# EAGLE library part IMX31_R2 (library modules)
PVS (02/06/2008) pin name 2.775V changed in 3.1V CT (05/03/2008): split component in two symbols added all names to pins as in schematic of CPU-module rev120.
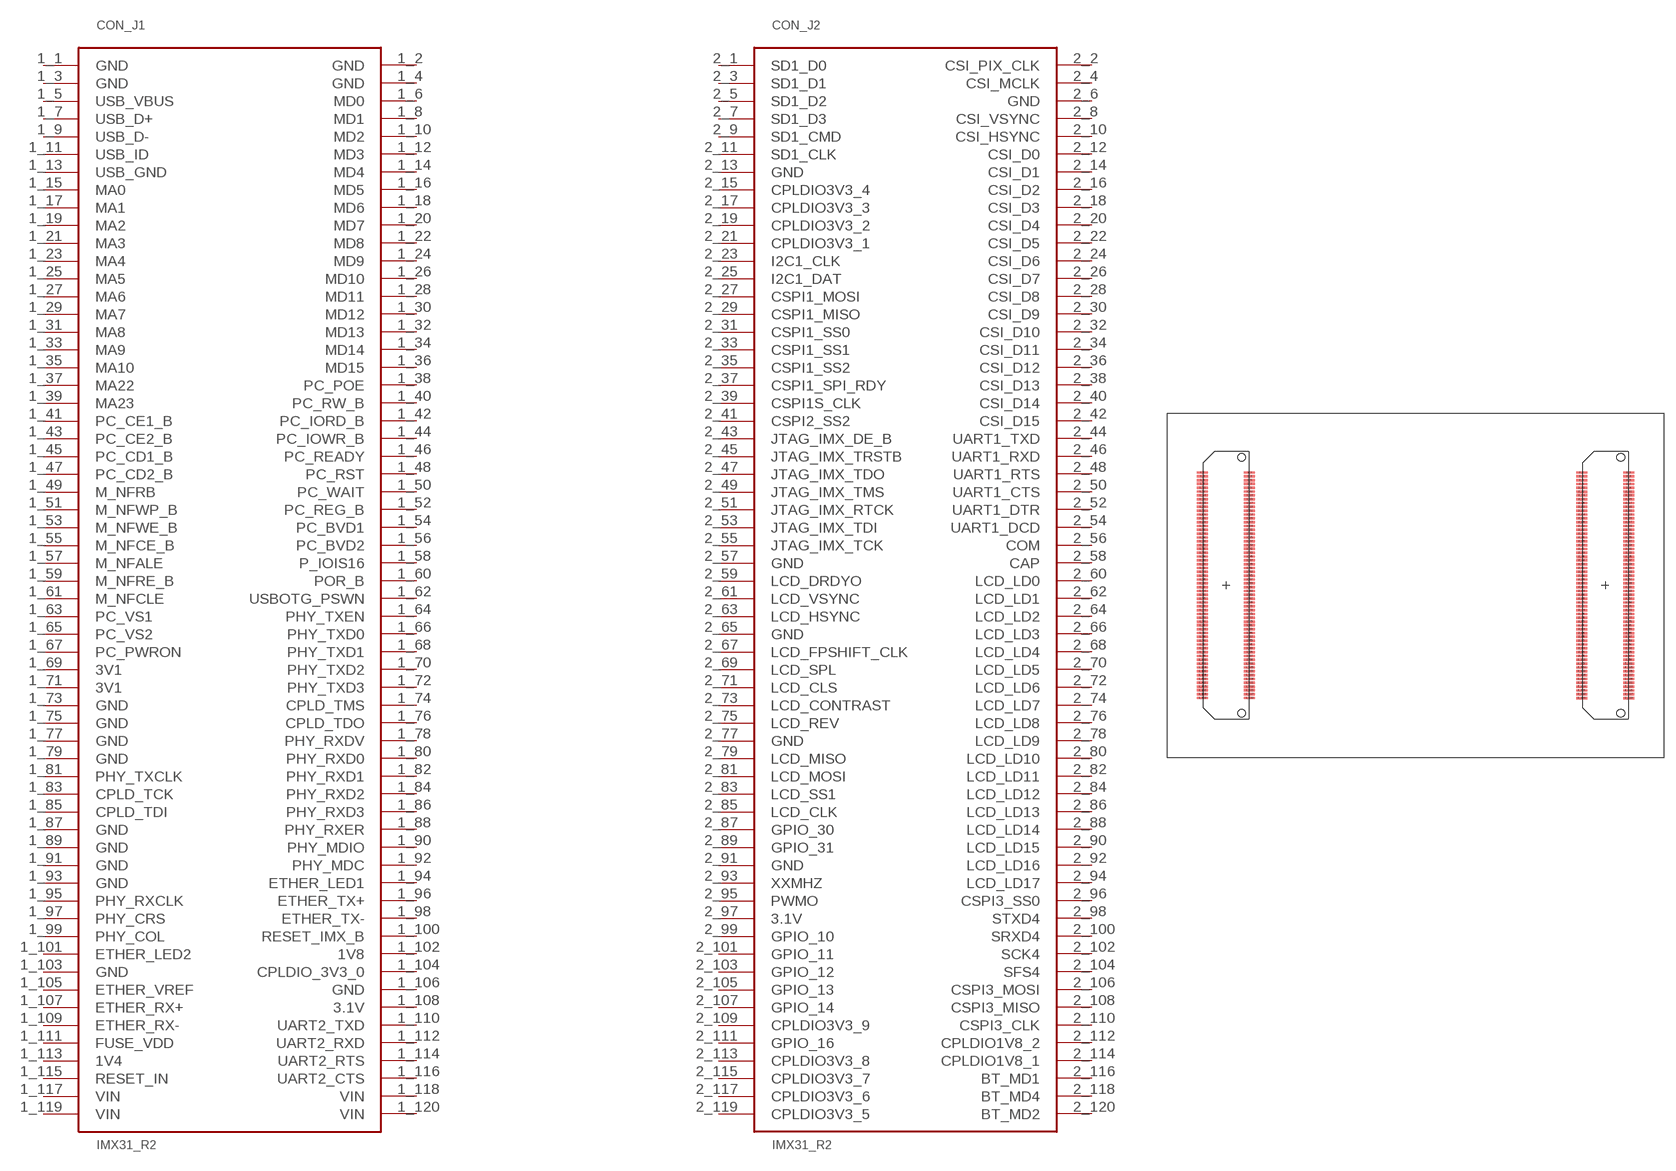
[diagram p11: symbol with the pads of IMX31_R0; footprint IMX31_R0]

Designator prefix CON; gates _J1=CPU_MODULE_J1-1 _J2=CPU_MODULE_J2-1

## IMX31_R2  [IMX31_R0]
1_1  _J1:GND
1_2  _J1:GND
1_3  _J1:GND
1_4  _J1:GND
1_5  _J1:USB_VBUS
1_6  _J1:MD0
1_7  _J1:USB_D+
1_8  _J1:MD1
1_9  _J1:USB_D-
1_10  _J1:MD2
1_11  _J1:USB_ID
1_12  _J1:MD3
1_13  _J1:USB_GND
1_14  _J1:MD4
1_15  _J1:MA0
1_16  _J1:MD5
1_17  _J1:MA1
1_18  _J1:MD6
1_19  _J1:MA2
1_20  _J1:MD7
1_21  _J1:MA3
1_22  _J1:MD8
1_23  _J1:MA4
1_24  _J1:MD9
1_25  _J1:MA5
1_26  _J1:MD10
1_27  _J1:MA6
1_28  _J1:MD11
1_29  _J1:MA7
1_30  _J1:MD12
1_31  _J1:MA8
1_32  _J1:MD13
1_33  _J1:MA9
1_34  _J1:MD14
1_35  _J1:MA10
1_36  _J1:MD15
1_37  _J1:MA22
1_38  _J1:PC_POE
1_39  _J1:MA23
1_40  _J1:PC_RW_B
1_41  _J1:PC_CE1_B
1_42  _J1:PC_IORD_B
1_43  _J1:PC_CE2_B
1_44  _J1:PC_IOWR_B
1_45  _J1:PC_CD1_B
1_46  _J1:PC_READY
1_47  _J1:PC_CD2_B
1_48  _J1:PC_RST
1_49  _J1:M_NFRB
1_50  _J1:PC_WAIT
1_51  _J1:M_NFWP_B
1_52  _J1:PC_REG_B
1_53  _J1:M_NFWE_B
1_54  _J1:PC_BVD1
1_55  _J1:M_NFCE_B
1_56  _J1:PC_BVD2
1_57  _J1:M_NFALE
1_58  _J1:P_IOIS16
1_59  _J1:M_NFRE_B
1_60  _J1:POR_B
1_61  _J1:M_NFCLE
1_62  _J1:USBOTG_PSWN
1_63  _J1:PC_VS1
1_64  _J1:PHY_TXEN
1_65  _J1:PC_VS2
1_66  _J1:PHY_TXD0
1_67  _J1:PC_PWRON
1_68  _J1:PHY_TXD1
1_69  _J1:3V1
1_70  _J1:PHY_TXD2
1_71  _J1:3V1
1_72  _J1:PHY_TXD3
1_73  _J1:GND
1_74  _J1:CPLD_TMS
1_75  _J1:GND
1_76  _J1:CPLD_TDO
1_77  _J1:GND
1_78  _J1:PHY_RXDV
1_79  _J1:GND
1_80  _J1:PHY_RXD0
1_81  _J1:PHY_TXCLK
1_82  _J1:PHY_RXD1
1_83  _J1:CPLD_TCK
1_84  _J1:PHY_RXD2
1_85  _J1:CPLD_TDI
1_86  _J1:PHY_RXD3
1_87  _J1:GND
1_88  _J1:PHY_RXER
1_89  _J1:GND
1_90  _J1:PHY_MDIO
1_91  _J1:GND
1_92  _J1:PHY_MDC
1_93  _J1:GND
1_94  _J1:ETHER_LED1
1_95  _J1:PHY_RXCLK
1_96  _J1:ETHER_TX+
1_97  _J1:PHY_CRS
1_98  _J1:ETHER_TX-
1_99  _J1:PHY_COL
1_100  _J1:RESET_IMX_B
1_101  _J1:ETHER_LED2
1_102  _J1:1V8
1_103  _J1:GND
1_104  _J1:CPLDIO_3V3_0
1_105  _J1:ETHER_VREF
1_106  _J1:GND
1_107  _J1:ETHER_RX+
1_108  _J1:3.1V
1_109  _J1:ETHER_RX-
1_110  _J1:UART2_TXD
1_111  _J1:FUSE_VDD
1_112  _J1:UART2_RXD
1_113  _J1:1V4
1_114  _J1:UART2_RTS
1_115  _J1:RESET_IN
1_116  _J1:UART2_CTS
1_117  _J1:VIN
1_118  _J1:VIN
1_119  _J1:VIN
1_120  _J1:VIN
2_1  _J2:SD1_D0
2_2  _J2:CSI_PIX_CLK
2_3  _J2:SD1_D1
2_4  _J2:CSI_MCLK
2_5  _J2:SD1_D2
2_6  _J2:GND
2_7  _J2:SD1_D3
2_8  _J2:CSI_VSYNC
2_9  _J2:SD1_CMD
2_10  _J2:CSI_HSYNC
2_11  _J2:SD1_CLK
2_12  _J2:CSI_D0
2_13  _J2:GND
2_14  _J2:CSI_D1
2_15  _J2:CPLDIO3V3_4
2_16  _J2:CSI_D2
2_17  _J2:CPLDIO3V3_3
2_18  _J2:CSI_D3
2_19  _J2:CPLDIO3V3_2
2_20  _J2:CSI_D4
2_21  _J2:CPLDIO3V3_1
2_22  _J2:CSI_D5
2_23  _J2:I2C1_CLK
2_24  _J2:CSI_D6
2_25  _J2:I2C1_DAT
2_26  _J2:CSI_D7
2_27  _J2:CSPI1_MOSI
2_28  _J2:CSI_D8
2_29  _J2:CSPI1_MISO
2_30  _J2:CSI_D9
2_31  _J2:CSPI1_SS0
2_32  _J2:CSI_D10
2_33  _J2:CSPI1_SS1
2_34  _J2:CSI_D11
2_35  _J2:CSPI1_SS2
2_36  _J2:CSI_D12
2_37  _J2:CSPI1_SPI_RDY
2_38  _J2:CSI_D13
2_39  _J2:CSPI1S_CLK
2_40  _J2:CSI_D14
2_41  _J2:CSPI2_SS2
2_42  _J2:CSI_D15
2_43  _J2:JTAG_IMX_DE_B
2_44  _J2:UART1_TXD
2_45  _J2:JTAG_IMX_TRSTB
2_46  _J2:UART1_RXD
2_47  _J2:JTAG_IMX_TDO
2_48  _J2:UART1_RTS
2_49  _J2:JTAG_IMX_TMS
2_50  _J2:UART1_CTS
2_51  _J2:JTAG_IMX_RTCK
2_52  _J2:UART1_DTR
2_53  _J2:JTAG_IMX_TDI
2_54  _J2:UART1_DCD
2_55  _J2:JTAG_IMX_TCK
2_56  _J2:COM
2_57  _J2:GND
2_58  _J2:CAP
2_59  _J2:LCD_DRDYO
2_60  _J2:LCD_LD0
2_61  _J2:LCD_VSYNC
2_62  _J2:LCD_LD1
2_63  _J2:LCD_HSYNC
2_64  _J2:LCD_LD2
2_65  _J2:GND
2_66  _J2:LCD_LD3
2_67  _J2:LCD_FPSHIFT_CLK
2_68  _J2:LCD_LD4
2_69  _J2:LCD_SPL
2_70  _J2:LCD_LD5
2_71  _J2:LCD_CLS
2_72  _J2:LCD_LD6
2_73  _J2:LCD_CONTRAST
2_74  _J2:LCD_LD7
2_75  _J2:LCD_REV
2_76  _J2:LCD_LD8
2_77  _J2:GND
2_78  _J2:LCD_LD9
2_79  _J2:LCD_MISO
2_80  _J2:LCD_LD10
2_81  _J2:LCD_MOSI
2_82  _J2:LCD_LD11
2_83  _J2:LCD_SS1
2_84  _J2:LCD_LD12
2_85  _J2:LCD_CLK
2_86  _J2:LCD_LD13
2_87  _J2:GPIO_30
2_88  _J2:LCD_LD14
2_89  _J2:GPIO_31
2_90  _J2:LCD_LD15
2_91  _J2:GND
2_92  _J2:LCD_LD16
2_93  _J2:XXMHZ
2_94  _J2:LCD_LD17
2_95  _J2:PWMO
2_96  _J2:CSPI3_SS0
2_97  _J2:3.1V
2_98  _J2:STXD4
2_99  _J2:GPIO_10
2_100  _J2:SRXD4
2_101  _J2:GPIO_11
2_102  _J2:SCK4
2_103  _J2:GPIO_12
2_104  _J2:SFS4
2_105  _J2:GPIO_13
2_106  _J2:CSPI3_MOSI
2_107  _J2:GPIO_14
2_108  _J2:CSPI3_MISO
2_109  _J2:CPLDIO3V3_9
2_110  _J2:CSPI3_CLK
2_111  _J2:GPIO_16
2_112  _J2:CPLDIO1V8_2
2_113  _J2:CPLDIO3V3_8
2_114  _J2:CPLDIO1V8_1
2_115  _J2:CPLDIO3V3_7
2_116  _J2:BT_MD1
2_117  _J2:CPLDIO3V3_6
2_118  _J2:BT_MD4
2_119  _J2:CPLDIO3V3_5
2_120  _J2:BT_MD2

## Footprint IMX31_R0 (pad centres in mm)
CT: 6 oct. 2008: changed drill of locking pins to 0.04" according to datasheet of -A option of connectors.
smd 1.448 x 0.305: 1_1 -21.714,14.755; 1_2 -27.886,14.755; 1_3 -21.714,14.255; 1_4 -27.886,14.255; 1_5 -21.714,13.755; 1_6 -27.886,13.755; 1_7 -21.714,13.255; 1_8 -27.886,13.255; 1_9 -21.714,12.755; 1_10 -27.886,12.755; 1_11 -21.714,12.255; 1_12 -27.886,12.255; 1_13 -21.714,11.755; 1_14 -27.886,11.755; 1_15 -21.714,11.255; 1_16 -27.886,11.255; 1_17 -21.714,10.755; 1_18 -27.886,10.755; 1_19 -21.714,10.255; 1_20 -27.886,10.255; 1_21 -21.714,9.755; 1_22 -27.886,9.755; 1_23 -21.714,9.255; 1_24 -27.886,9.255; 1_25 -21.714,8.755; 1_26 -27.886,8.755; 1_27 -21.714,8.255; 1_28 -27.886,8.255; 1_29 -21.714,7.755; 1_30 -27.886,7.755; 1_31 -21.714,7.255; 1_32 -27.886,7.255; 1_33 -21.714,6.755; 1_34 -27.886,6.755; 1_35 -21.714,6.255; 1_36 -27.886,6.255; 1_37 -21.714,5.755; 1_38 -27.886,5.755; 1_39 -21.714,5.255; 1_40 -27.886,5.255; 1_41 -21.714,4.755; 1_42 -27.886,4.755; 1_43 -21.714,4.255; 1_44 -27.886,4.255; 1_45 -21.714,3.755; 1_46 -27.886,3.755; 1_47 -21.714,3.255; 1_48 -27.886,3.255; 1_49 -21.714,2.755; 1_50 -27.886,2.755; 1_51 -21.714,2.255; 1_52 -27.886,2.255; 1_53 -21.714,1.755; 1_54 -27.886,1.755; 1_55 -21.714,1.255; 1_56 -27.886,1.255; 1_57 -21.714,0.755; 1_58 -27.886,0.755; 1_59 -21.714,0.255; 1_60 -27.886,0.255; 1_61 -21.714,-0.248; 1_62 -27.886,-0.248; 1_63 -21.714,-0.748; 1_64 -27.886,-0.748; 1_65 -21.714,-1.248; 1_66 -27.886,-1.248; 1_67 -21.714,-1.748; 1_68 -27.886,-1.748; 1_69 -21.714,-2.248; 1_70 -27.886,-2.248; 1_71 -21.714,-2.748; 1_72 -27.886,-2.748; 1_73 -21.714,-3.248; 1_74 -27.886,-3.248; 1_75 -21.714,-3.748; 1_76 -27.886,-3.748; 1_77 -21.714,-4.248; 1_78 -27.886,-4.248; 1_79 -21.714,-4.748; 1_80 -27.886,-4.748; 1_81 -21.714,-5.248; 1_82 -27.886,-5.248; 1_83 -21.714,-5.748; 1_84 -27.886,-5.748; 1_85 -21.714,-6.248; 1_86 -27.886,-6.248; 1_87 -21.714,-6.748; 1_88 -27.886,-6.748; 1_89 -21.714,-7.248; 1_90 -27.886,-7.248; 1_91 -21.714,-7.748; 1_92 -27.886,-7.748; 1_93 -21.714,-8.248; 1_94 -27.886,-8.248; 1_95 -21.714,-8.748; 1_96 -27.886,-8.748; 1_97 -21.714,-9.248; 1_98 -27.886,-9.248; 1_99 -21.714,-9.748; 1_100 -27.886,-9.748; 1_101 -21.714,-10.248; 1_102 -27.886,-10.248; 1_103 -21.714,-10.748; 1_104 -27.886,-10.748; 1_105 -21.714,-11.248; 1_106 -27.886,-11.248; 1_107 -21.714,-11.748; 1_108 -27.886,-11.748; 1_109 -21.714,-12.248; 1_110 -27.886,-12.248; 1_111 -21.714,-12.748; 1_112 -27.886,-12.748; 1_113 -21.714,-13.248; 1_114 -27.886,-13.248; 1_115 -21.714,-13.748; 1_116 -27.886,-13.748; 1_117 -21.714,-14.248; 1_118 -27.886,-14.248; 1_119 -21.714,-14.748; 1_120 -27.886,-14.748; 2_1 27.885,14.752; 2_2 21.713,14.752; 2_3 27.885,14.252; 2_4 21.713,14.252; 2_5 27.885,13.752; 2_6 21.713,13.752; 2_7 27.885,13.252; 2_8 21.713,13.252; 2_9 27.885,12.752; 2_10 21.713,12.752; 2_11 27.885,12.252; 2_12 21.713,12.252; 2_13 27.885,11.752; 2_14 21.713,11.752; 2_15 27.885,11.252; 2_16 21.713,11.252; 2_17 27.885,10.752; 2_18 21.713,10.752; 2_19 27.885,10.252; 2_20 21.713,10.252; 2_21 27.885,9.752; 2_22 21.713,9.752; 2_23 27.885,9.252; 2_24 21.713,9.252; 2_25 27.885,8.752; 2_26 21.713,8.752; 2_27 27.885,8.252; 2_28 21.713,8.252; 2_29 27.885,7.752; 2_30 21.713,7.752; 2_31 27.885,7.252; 2_32 21.713,7.252; 2_33 27.885,6.752; 2_34 21.713,6.752; 2_35 27.885,6.252; 2_36 21.713,6.252; 2_37 27.885,5.752; 2_38 21.713,5.752; 2_39 27.885,5.252; 2_40 21.713,5.252; 2_41 27.885,4.752; 2_42 21.713,4.752; 2_43 27.885,4.252; 2_44 21.713,4.252; 2_45 27.885,3.752; 2_46 21.713,3.752; 2_47 27.885,3.251; 2_48 21.713,3.251; 2_49 27.885,2.751; 2_50 21.713,2.751; 2_51 27.885,2.251; 2_52 21.713,2.251; 2_53 27.885,1.752; 2_54 21.713,1.752; 2_55 27.885,1.252; 2_56 21.713,1.252; 2_57 27.885,0.751; 2_58 21.713,0.751; 2_59 27.885,0.252; 2_60 21.713,0.252; 2_61 27.885,-0.252; 2_62 21.713,-0.252; 2_63 27.884,-0.754; 2_64 21.713,-0.751; 2_65 27.885,-1.252; 2_66 21.713,-1.252; 2_67 27.885,-1.752; 2_68 21.713,-1.752; 2_69 27.885,-2.252; 2_70 21.713,-2.252; 2_71 27.885,-2.752; 2_72 21.713,-2.752; 2_73 27.885,-3.252; 2_74 21.713,-3.252; 2_75 27.885,-3.752; 2_76 21.713,-3.752; 2_77 27.885,-4.252; 2_78 21.713,-4.252; 2_79 27.885,-4.752; 2_80 21.713,-4.752; 2_81 27.885,-5.252; 2_82 21.713,-5.252; 2_83 27.885,-5.752; 2_84 21.713,-5.752; 2_85 27.885,-6.252; 2_86 21.713,-6.252; 2_87 27.885,-6.752; 2_88 21.713,-6.752; 2_89 27.885,-7.252; 2_90 21.713,-7.252; 2_91 27.885,-7.752; 2_92 21.713,-7.752; 2_93 27.885,-8.252; 2_94 21.713,-8.252; 2_95 27.885,-8.752; 2_96 21.713,-8.752; 2_97 27.885,-9.252; 2_98 21.713,-9.252; 2_99 27.885,-9.752; 2_100 21.713,-9.752; 2_101 27.885,-10.252; 2_102 21.713,-10.252; 2_103 27.885,-10.752; 2_104 21.713,-10.752; 2_105 27.885,-11.252; 2_106 21.713,-11.252; 2_107 27.885,-11.752; 2_108 21.713,-11.752; 2_109 27.885,-12.252; 2_110 21.713,-12.252; 2_111 27.885,-12.752; 2_112 21.713,-12.752; 2_113 27.885,-13.252; 2_114 21.713,-13.252; 2_115 27.885,-13.752; 2_116 21.713,-13.752; 2_117 27.885,-14.252; 2_118 21.713,-14.252; 2_119 27.885,-14.752; 2_120 21.713,-14.752
hole 1.016 at -22.768,16.74
hole 1.016 at -22.768,-16.735
hole 1.016 at 26.831,16.736
hole 1.016 at 26.831,-16.739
